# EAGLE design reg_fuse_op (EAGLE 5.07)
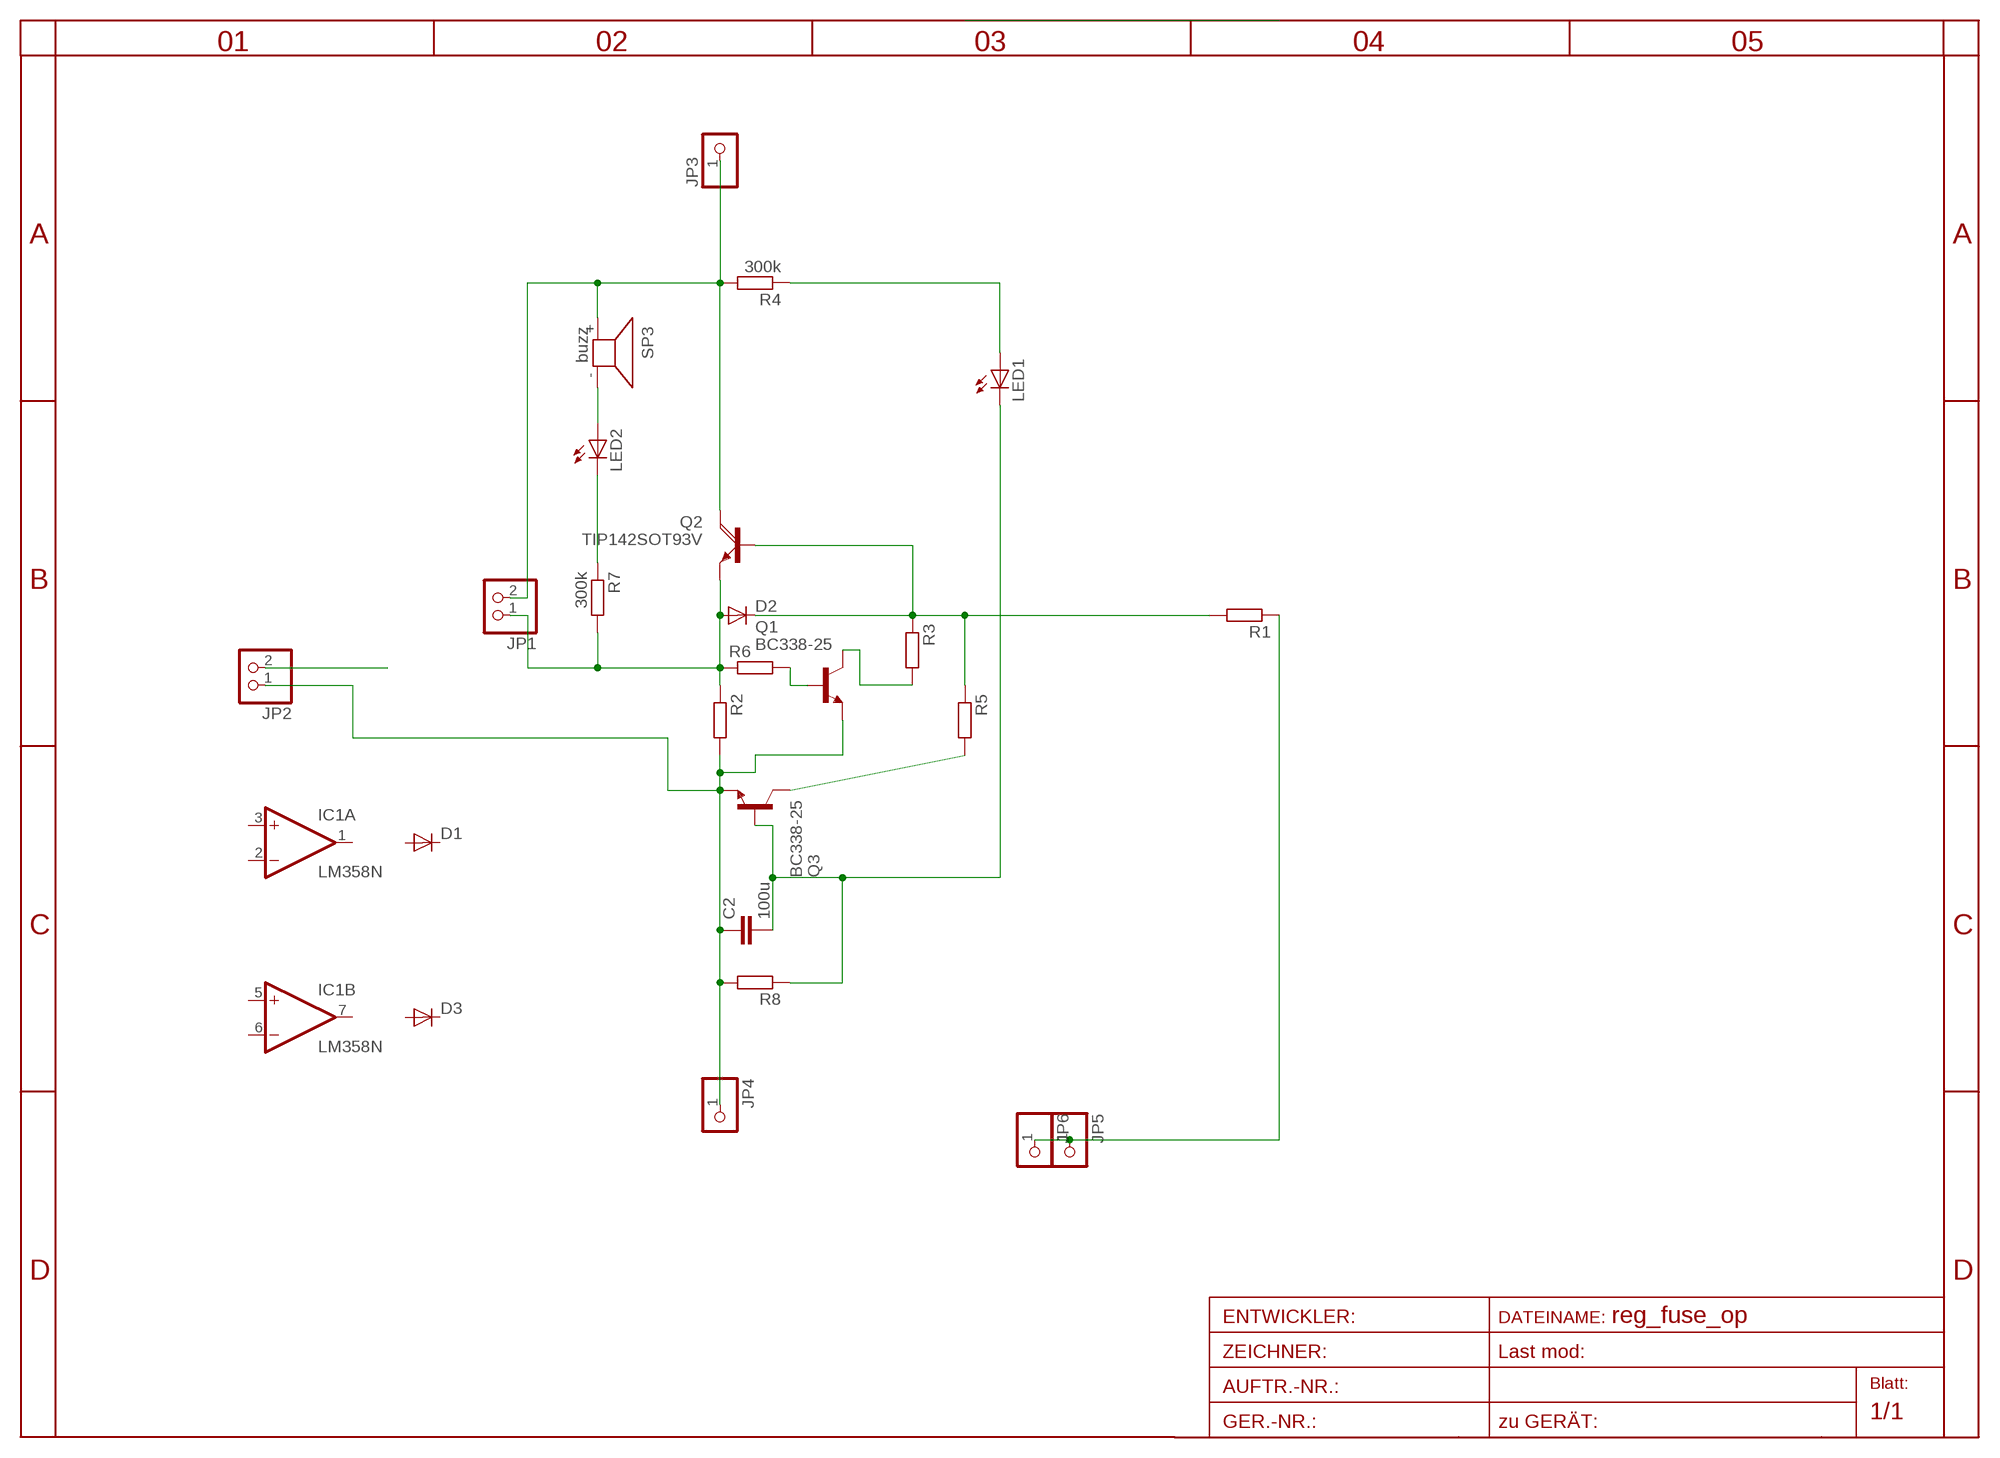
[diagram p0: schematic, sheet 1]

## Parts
C2  100u  C-EU025-024X044  [C025-024X044]
D1  DIODE-D-5  [D-5]
D2  DIODE-D-5  [D-5]
D3  DIODE-D-5  [D-5]
IC1  LM358N  [DIL08]
JP1  PINHD-1X2/90  [1X02/90]
JP2  PINHD-1X2/90  [1X02/90]
JP3  PINHD-1X12MM3  [1X2MM3]
JP4  PINHD-1X12MM3  [1X2MM3]
JP5  PINHD-1X12MM3  [1X2MM3]
JP6  PINHD-1X12MM3  [1X2MM3]
LED1  LED3MM  [LED3MM]
LED2  LED5MM  [LED5MM]
Q1  BC338-25  [TO92-EBC]
Q2  TIP142SOT93V  [SOT93V]
Q3  BC338-25  [TO92-EBC]
R1  R-EU_0204/5  [0204/5]
R2  R-EU_0411/12  [0411/12]
R3  R-EU_0204/5  [0204/5]
R4  300k  R-EU_0204/5  [0204/5]
R5  R-EU_0204/5  [0204/5]
R6  R-EU_0204/7  [0204/7]
R7  300k  R-EU_0204/5  [0204/5]
R8  R-EU_0204/5  [0204/5]
SP3  buzz  KSS12017MM  [KSS1202]

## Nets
N$1: JP5.1 JP6.1 R1.1
N$3: D2.A JP1.1 Q2.E R2.1 R6.1 R7.2
N$4: D2.C Q2.B R1.2 R3.1 R5.1
N$5: Q3.C R5.2
N$6: Q1.B R6.2
N$7: Q1.C R3.2
N$8: JP1.2 JP3.1 Q2.C R4.2 SP3.+
N$9: LED2.K(C) R7.1
N$11: LED1.A R4.1
N$12: C2.2 LED1.K(C) Q3.B R8.1
N$13: LED2.A SP3.-
V+: JP2.2
V-: C2.1 JP2.1 JP4.1 Q1.E Q3.E R2.2 R8.2
Unconnected: D1.A D1.C D3.A D3.C IC1.1(A:OUT) IC1.2(A:-IN) IC1.3(A:+IN) IC1.5(B:+IN) IC1.6(B:-IN) IC1.7(B:OUT)

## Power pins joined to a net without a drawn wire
V+: IC1.8(P:V+)
V-: IC1.4(P:V-)

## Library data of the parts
C2 = rcl-2:C-EU: CAPACITOR, European symbol
D1-D3 = diode-1:DIODE-: DIODE
IC1 = linear:LM358: OP AMP also LM158; LM258; LM2904 Source: http://cache.national.com/ds/LM/LM158.pdf
JP1 JP2 = pinhead:PINHD-1X2: PIN HEADER
JP3-JP6 = pinhead:PINHD-1X1: PIN HEADER
LED1 LED2 = led:LED: LED
Q1 Q3 = transistor-npn:BC338*: NPN Transistor
Q2 = transistor-power:TIP142: NPN DARLINGTON TRANSISTOR
R1-R8 = rcl-2:R-EU_: RESISTOR, European symbol
SP3 = buzzer:KSS1201: SPEAKER

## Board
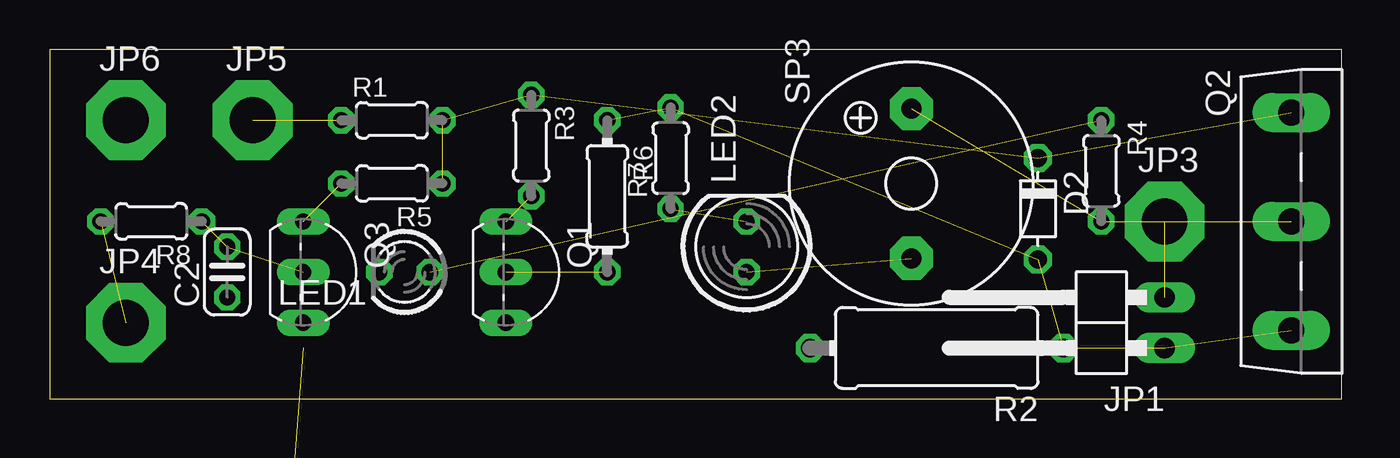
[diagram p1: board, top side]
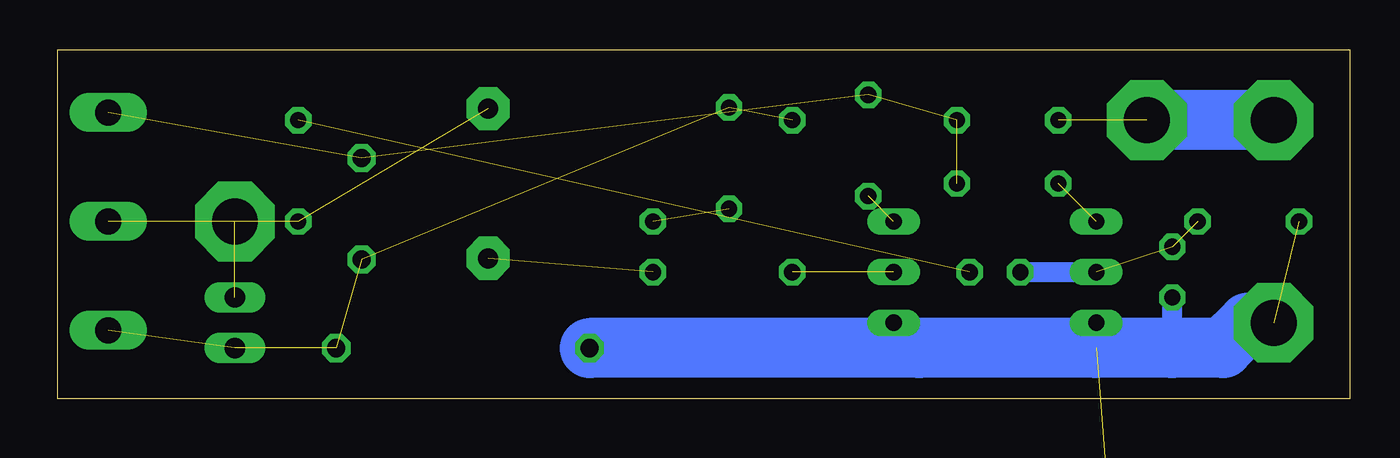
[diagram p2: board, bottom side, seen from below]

Size 64.77 x 17.5 mm. Coordinates in mm from the lower left corner, seen from the top.
Outline: 0,0 64.77,0 64.77,17.5 0,17.5 0,0
Copper layers (1*16): Top 0.035mm / dielectric 1.5mm / Bottom 0.035mm
Design rules "default": minimum track width 10mil, minimum drill 24mil, track to track 8mil, track to pad 8mil, pad to pad 8mil, via to via 8mil, smd to smd 8mil, copper to edge 40mil, drill to drill 8mil, minimum pad ring 10mil, minimum via ring 8mil, stop-mask expansion 4mil, vias tented up to drill 0mil, thermal gap 10mil

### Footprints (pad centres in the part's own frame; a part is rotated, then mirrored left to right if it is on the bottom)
C025-024X044 = drill 0.813 octagon: 1 -1.27,0; 2 1.27,0
D-5 = drill 0.9 octagon: A 2.54,0; C -2.54,0
DIL08 = drill 0.813 pad 1.27 round: 1 -3.81,-3.81; 2 -1.27,-3.81; 3 1.27,-3.81; 4 3.81,-3.81; 5 3.81,3.81; 6 1.27,3.81; 7 -1.27,3.81; 8 -3.81,3.81
1X02/90 = drill 1.016 long: 1 -1.27,-3.81; 2 1.27,-3.81
1X2MM3 = drill 2.3 pad 4 octagon: 1 0,0
LED3MM = drill 0.813 octagon: A -1.27,0; K 1.27,0
LED5MM = drill 0.813 octagon: A -1.27,0; K 1.27,0
TO92-EBC = drill 0.813 long: B 0,-1.27; C -2.54,-1.27; E 2.54,-1.27
SOT93V = drill 1.3 pad 1.676 long: B -5.461,-2.54; C 0,-2.54; E 5.461,-2.54
0204/5 = drill 0.813 octagon: 1 -2.54,0; 2 2.54,0
0411/12 = drill 0.914 octagon: 1 -6.35,0; 2 6.35,0
0204/7 = drill 0.813 octagon: 1 -3.81,0; 2 3.81,0
KSS1202 = drill 1 pad 2.159 octagon: + 3.75,0; - -3.75,0

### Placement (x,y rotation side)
C2  8.89,6.35 90 top
D1  not placed on the board
D2  49.53,9.53 270 top
D3  not placed on the board
IC1  not placed on the board
JP1  52.07,3.81 90 top
JP2  not placed on the board
JP3  55.88,8.89 0 top
JP4  3.81,3.81 0 top
JP5  10.16,13.97 0 top
JP6  3.81,13.97 0 top
LED1  17.78,6.35 180 top
LED2  34.92,7.62 90 top
Q1  24.13,6.35 270 top
Q2  64.77,8.89 270 top
Q3  13.97,6.35 270 top
R1  17.14,13.97 0 top
R2  44.45,2.54 180 top
R3  24.13,12.7 270 top
R4  52.7,11.43 270 top
R5  17.14,10.79 180 top
R6  27.94,10.16 270 top
R7  31.11,12.06 90 top
R8  5.08,8.89 180 top
SP3  43.18,10.79 90 top

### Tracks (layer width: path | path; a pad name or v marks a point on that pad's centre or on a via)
N$1  (1 unrouted)
  Bottom 3: JP6.1 JP5.1
N$3  (5 unrouted)
N$4  (4 unrouted)
N$5  (1 unrouted)
N$6  (1 unrouted)
N$7  (1 unrouted)
N$8  (4 unrouted)
N$9  (1 unrouted)
N$11  (1 unrouted)
N$12  (2 unrouted)
  Bottom 1: LED1.K Q3.B
N$13  (1 unrouted)
V+  (1 unrouted)
V-  (3 unrouted)
  Bottom 1: 12.7,2.54 Q3.E | 21.59,2.54 Q1.E | 8.89,2.54 C2.1
  Bottom 3: JP4.1 5.08,3.81 6.35,2.54 8.89,2.54 12.7,2.54 21.59,2.54 R2.2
